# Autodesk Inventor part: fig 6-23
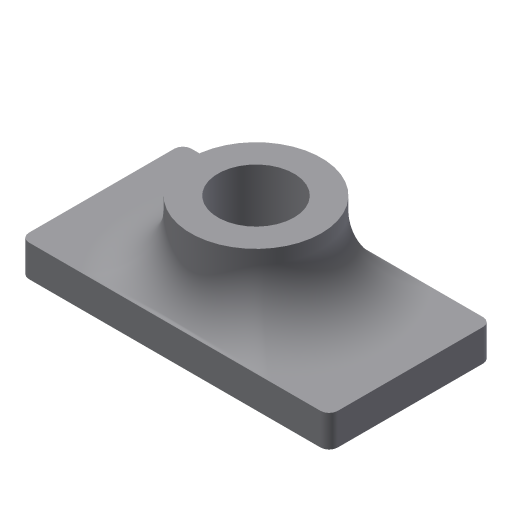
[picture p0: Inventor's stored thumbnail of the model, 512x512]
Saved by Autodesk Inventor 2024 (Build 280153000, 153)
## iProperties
Created: 2004-05
Part Number: fig 6-23
Document SubType Name: Modeling
Designer: CADCIM Technologies
Manufacturer: Standard
Standards Organization: Custom
Density: 1 g/cm^3
Material: Generic
Appearance: Default
Author: CADCIM Technologies
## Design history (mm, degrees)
sketch "Sketch1"
  geometry: L1 (-39.276, -18.692)-(33.721, -18.692); L2 (33.721, -18.692)-(33.721, 19.728); L3 (33.721, 19.728)-(-39.276, 19.728); L4 (-39.276, 19.728)-(-39.276, -18.692)
  constraints: 8 end point, 2 parallel, 1 horizontal, 1 perpendicular
extrude "Extrusion1" new body sketch "Sketch1" distance "d0" = 7.5; taper "d1" = 0 deg
fillet "Fillet1" dims "d2" = 2
sketch "Sketch2"
  geometry: C1 r 15.456 at (-2.778, 0.518)
  constraints: 1 centre point
extrude "Extrusion2" join sketch "Sketch2" distance "d3" = 17.25; taper "d4" = 0 deg
hole "Hole1" diameter "d8" = 18; stored, may be unused: countersink angle "d12" = 90 deg, drill point angle "d14" = 118 deg; dims "d6" = 10, "d7" = 10, "d9" = 6, "d10" = 4, "d11" = 2, "d13" = 8
fillet "Fillet2" dims "d5" = 14
body "Solid1"
